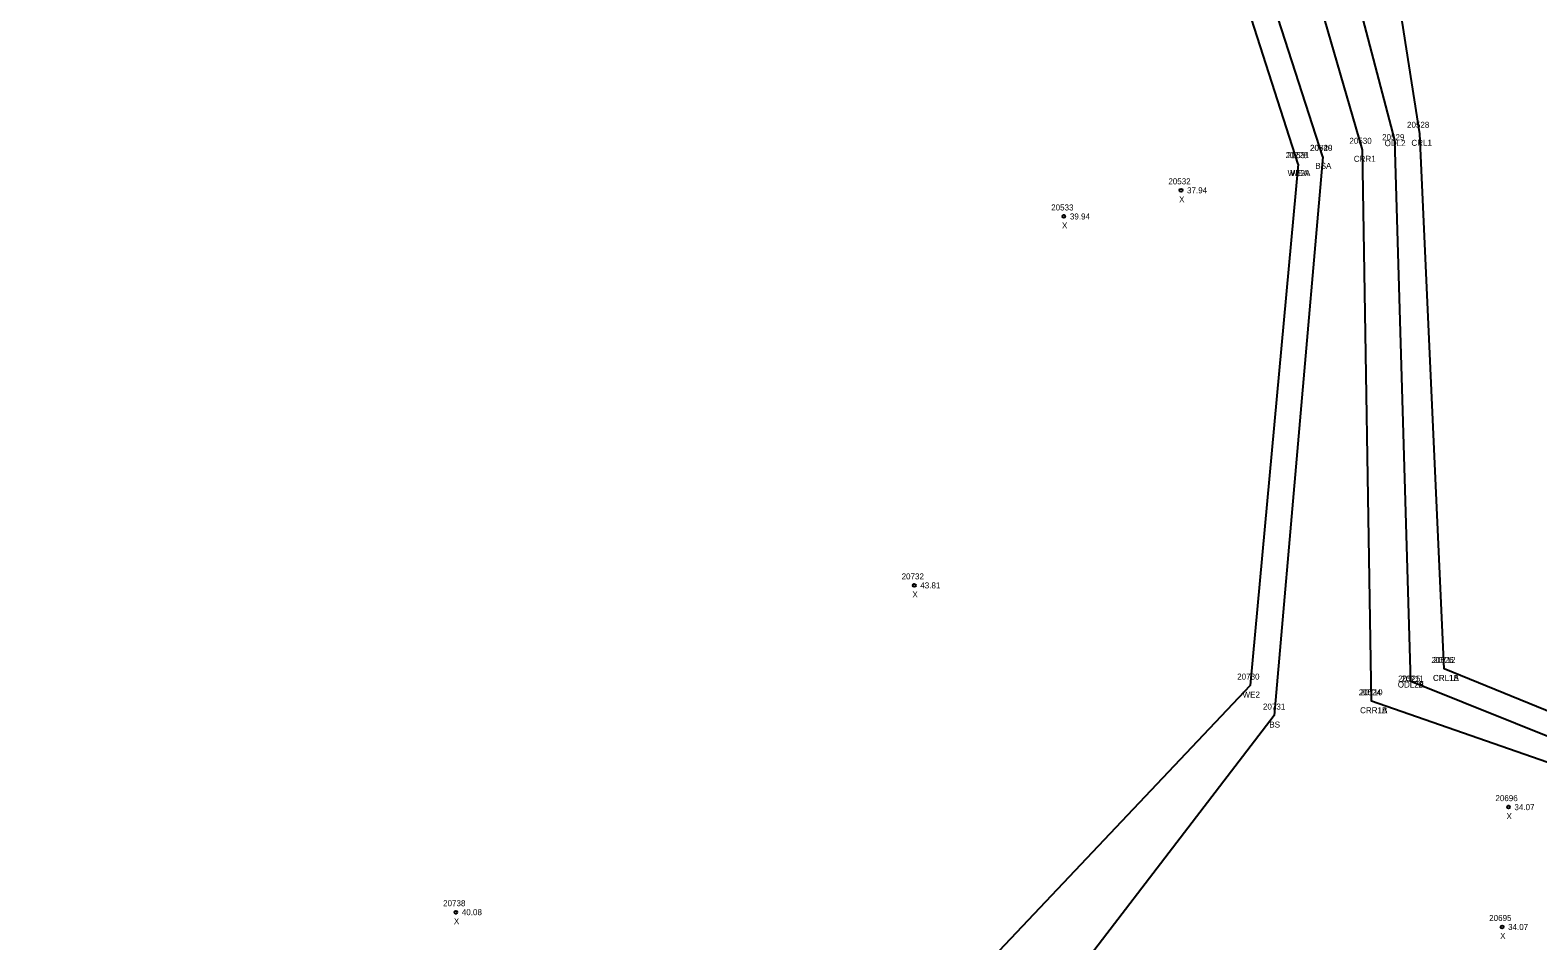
# Model space of a CAD drawing. Extents: x 2445178 to 2446260, y 791158 to 792318.
# Drawn here: x 2445179.6 to 2445430.8, y 791780.8 to 791932.6 of the extents above; entities that cross this region are included whole.
import ezdxf

# ---------------------------------------------------------------- set-up
doc = ezdxf.new("R2010")
doc.units = 0
for name, color, linetype in [('RD_DTM_BkLn2', 7, 'Continuous'), ('RD_EX_H2O', 7, 'Continuous'), ('RD_EX_H2O_txCode', 7, 'Continuous'), ('RD_Sketch8', 7, 'Continuous'), ('RD_SMD_Locator', 7, 'Continuous'), ('RD_SMD_Misc', 7, 'Continuous')]:
    doc.layers.add(name, color=color, linetype=linetype)

msp = doc.modelspace()

# ---------------------------------------------------------------- linework, layer by layer
at = {"layer": 'RD_DTM_BkLn2'}
for points in [[(2445394.99, 791911.52), (2445379, 791961.15), (2445299.27, 792041.56), (2445211.16, 792087.81)], [(2445394.99, 791911.52), (2445386.85, 791818.37), (2445340.06, 791757.26), (2445258.15, 791749.35), (2445179.64, 791718.55)]]:
    msp.add_lwpolyline(points, dxfattribs=at)
at = {"layer": 'RD_EX_H2O'}
for points in [[(2445415.21, 791826.15), (2445411.13, 791915.36), (2445401.26, 791978.48), (2445346.75, 792066.4), (2445347.89, 792130.96), (2445327.72, 792154.04), (2445265.04, 792188.92)], [(2445409.65, 791824.04), (2445406.98, 791914.3), (2445391.36, 791973.89), (2445340.62, 792062.76), (2445342.84, 792131.55), (2445326.53, 792149.18), (2445255.41, 792171.39)], [(2445403.09, 791820.76), (2445401.57, 791912.69), (2445385.3, 791968.86), (2445336.54, 792059.75), (2445337.52, 792129.63), (2445324.7, 792141.79), (2445250.6, 792162.62)], [(2445390.88, 791910.3), (2445375.84, 791957.27), (2445276.8, 792030.59), (2445204.16, 792074.54)], [(2445390.88, 791910.3), (2445382.88, 791823.37), (2445332.21, 791769.8), (2445259.4, 791752.08), (2445179.59, 791723.55)], [(2445544.99, 791749.08), (2445517.8, 791768.36), (2445478.59, 791760.86), (2445463.48, 791763.9), (2445460.87, 791773.93), (2445455.89, 791809.54), (2445415.21, 791826.15)], [(2445536.09, 791752.19), (2445517.24, 791765.41), (2445479.3, 791757.52), (2445462.61, 791759.06), (2445455.58, 791771.48), (2445452.95, 791806.64), (2445409.65, 791824.04)], [(2445530.12, 791747.41), (2445515.88, 791756.64), (2445479.19, 791754.53), (2445461.81, 791756.69), (2445452.6, 791771.81), (2445450.18, 791804.36), (2445403.09, 791820.76)]]:
    msp.add_lwpolyline(points, dxfattribs=at)
at = {"layer": 'RD_SMD_Locator'}
for centre, radius in [((2445411.13, 791915.36), 0.001), ((2445401.57, 791912.69), 0.001), ((2445406.98, 791914.3), 0.001), ((2445390.88, 791910.3), 0.001), ((2445390.88, 791910.3), 0.001), ((2445394.99, 791911.52), 0.001), ((2445394.99, 791911.52), 0.001), ((2445371.36, 791905.94), 0.25), ((2445351.84, 791901.58), 0.25), ((2445326.91, 791840.07), 0.25), ((2445415.21, 791826.15), 0.001), ((2445415.21, 791826.15), 0.001), ((2445382.88, 791823.37), 0.001), ((2445409.65, 791824.04), 0.001), ((2445409.65, 791824.04), 0.001), ((2445403.09, 791820.76), 0.001), ((2445403.09, 791820.76), 0.001), ((2445386.85, 791818.37), 0.001), ((2445425.91, 791803.1), 0.25), ((2445250.52, 791785.59), 0.25), ((2445424.85, 791783.13), 0.25)]:
    msp.add_circle(centre, radius, dxfattribs=at)

# ---------------------------------------------------------------- texts
at = {"layer": 'RD_EX_H2O_txCode'}
for s, p in [('20529', (2445404.86, 791914.3)), ('20528', (2445409.01, 791916.36)), ('20530', (2445399.41, 791913.69)), ('ODL2', (2445405.28, 791913.3)), ('CRL1', (2445409.74, 791913.36)), ('20728', (2445388.76, 791911.3)), ('20531', (2445389.04, 791911.3)), ('CRR1', (2445400.15, 791910.69)), ('WE2A', (2445389.12, 791908.3)), ('WEA', (2445389.57, 791908.3)), ('20526', (2445413.07, 791827.15)), ('20712', (2445413.38, 791827.15)), ('20730', (2445380.72, 791824.37)), ('20525', (2445407.53, 791824.04)), ('20711', (2445408.1, 791824.04)), ('CRL1A', (2445413.33, 791824.15)), ('CRL1B', (2445413.35, 791824.15)), ('WE2', (2445381.61, 791821.37)), ('20524', (2445400.97, 791821.76)), ('20710', (2445401.22, 791821.76)), ('ODL2A', (2445407.47, 791823.04)), ('ODL2B', (2445407.48, 791823.04)), ('CRR1A', (2445401.19, 791818.76)), ('CRR1B', (2445401.2, 791818.76))]:
    msp.add_text(s, height=1, dxfattribs=at).set_placement(p)
at = {"layer": 'RD_Sketch8'}
for s, p in [('20532', (2445369.24, 791906.94)), ('X', (2445371.04, 791903.94)), ('37.94', (2445372.36, 791905.44)), ('20533', (2445349.72, 791902.58)), ('X', (2445351.52, 791899.58)), ('39.94', (2445352.84, 791901.08)), ('20732', (2445324.8, 791841.07)), ('43.81', (2445327.91, 791839.57)), ('X', (2445326.6, 791838.07)), ('20696', (2445423.74, 791804.1)), ('X', (2445425.59, 791801.1)), ('34.07', (2445426.91, 791802.6)), ('20738', (2445248.4, 791786.59)), ('X', (2445250.2, 791783.59)), ('40.08', (2445251.52, 791785.09)), ('20695', (2445422.7, 791784.13)), ('X', (2445424.53, 791781.13)), ('34.07', (2445425.85, 791782.63))]:
    msp.add_text(s, height=1, dxfattribs=at).set_placement(p)
at = {"layer": 'RD_SMD_Misc'}
for s, p in [('20540', (2445392.84, 791912.52)), ('20729', (2445392.88, 791912.52)), ('BSA', (2445393.73, 791909.52)), ('BSA', (2445393.73, 791909.52)), ('20731', (2445385.01, 791819.37)), ('BS', (2445386.07, 791816.37))]:
    msp.add_text(s, height=1, dxfattribs=at).set_placement(p)

doc.saveas('drawing.dxf')
